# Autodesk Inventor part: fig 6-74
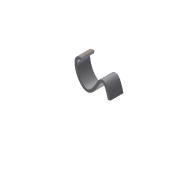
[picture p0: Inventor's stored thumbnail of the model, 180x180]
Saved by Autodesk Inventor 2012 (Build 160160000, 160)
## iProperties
Shininess: 64.0
Length Units: 11269
Angle Units: 11279
Time Units: 11290
Mass Units: 11283
Length Display Precision: 3
Angle Display Precision: 2
Compacted: True
Part Number: fig 6-74
Document SubType Name: Modeling
Created: 2002-12
Designer: deepak
Density: 1 g/cm^3
Material: Default
Density: 0.0
Volumn: 0.0
Area: 0.0
PropertySet Name: Model Information
Control State: 0
Master: False
Checked Out: False
Author: deepak
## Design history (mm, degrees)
sketch "Sketch1"
  geometry: 5 further points
  constraints: 5 other
extrude_surface "ExtrusionSrf1" sketch "Sketch1" dims "d0" = 20, "d1" = 0
thicken "Thicken2" dims "d6" = 4, "d7" = 4
body "Solid1"
body "Srf1"
